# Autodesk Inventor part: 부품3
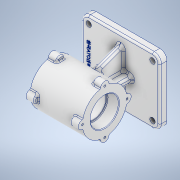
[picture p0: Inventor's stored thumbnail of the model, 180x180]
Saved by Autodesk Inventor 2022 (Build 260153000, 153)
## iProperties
Created: 2023-05
Part Number: 부품3
Material: 알루미늄 6061
Document SubType Name: Modeling
Designer: Admin
Density: 2.7 g/cm^3
Appearance: 알루미늄 - 평지
Mass: 1215.69 g
Surface Area: 797.962 cm^2
Volume: 450.254 cm^3
Author: Admin
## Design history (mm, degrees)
sketch "스케치1"
  geometry: L1 (-65, 55)-(65, 55); L2 (65, 55)-(65, -55); L3 (65, -55)-(-65, -55); L4 (-65, -55)-(-65, 55); L5 (-91, 0)-(91, 0) reference; L6 (0, -77)-(0, 77) reference; 1 further point
  constraints: 8 end point, 2 parallel, 1 horizontal, 1 perpendicular, 2 other
  dimensions: "d0" = 130 distance of L1.start L1.end; "d1" = 110 distance of L1.end L2.end
extrude "돌출1" new body sketch "스케치1" stored distance "d2" = 12; taper "d3" = 0 deg
sketch "스케치2"
  geometry: L1 (95.889, 76)-(-83.31, 76); L2 (-65, -6)-(65, -6) reference; L3 (-43.5, 76)-(43.5, 76); L4 (43.5, 76)-(43.5, 113); L5 (43.5, 113)-(-43.5, 113); L6 (-43.5, 113)-(-43.5, 76); L7 (0, -29.8)-(0, 136.8) reference; 2 further points
  constraints: 10 end point, 2 horizontal, 2 parallel, 1 perpendicular, 1 point on line, 1 other
  dimensions: "d4" = 82 distance between parallel lines of L2 L1; "d5" = 74 diameter of L5.end L1; "d6" = 87 distance of L4.end L5.end
revolve "회전1" sketch "스케치2" stored, may be unused: angle "d7" = 90 deg
sketch "스케치3"
  geometry: L1 (65, 6)-(-65, 6) reference; L2 (20, 6)-(20, 62.593); L3 (20, 62.593)-(-20, 62.593); L4 (-20, 62.593)-(-20, 6); L5 (20, 6)-(-20, 6); L6 (0, -29.8)-(0, 136.8) reference; 1 further point
  constraints: 8 end point, 3 perpendicular, 2 point on line, 1 collinear, 1 other
  dimensions: "d8" = 40 distance of L2.end L3.end; "d9" = 56.59267 distance of L3.end L4.end
extrude "돌출2" join sketch "스케치3" stored distance "d10" = 10; taper "d11" = 0 deg
sketch "스케치4"
  geometry: L1 (55, 6)-(-55, 6) reference; L2 (-41, 6)-(-14.452, 78.94); L3 (-55, 6)-(-55, -6) reference; 1 further point
  constraints: 2 end point, 1 point on line
  dimensions: "d12" = 110 deg angle of L1 L2; "d13" = 14 distance from line of L3 L2.start
feature "리브1" sketch "스케치4" dims "d14" = 1, "d15" = 10, "d16" = 0, "d17" = 0, "d18" = 1, "d19" = 1
sketch "스케치5"
  geometry: L1 (102.925, 76)-(-132.789, 76); L2 (65, -6)-(-65, -6) reference; L3 (-43.5, 39)-(-43.5, 113) reference; L4 (-43.5, 76)-(-24.5, 76); L5 (-24.5, 76)-(-24.5, 99.5); L6 (-24.5, 99.5)-(-43.5, 99.5); L7 (-43.5, 99.5)-(-43.5, 76); L8 (-24.5, 76)-(24.5, 76); L9 (24.5, 76)-(24.5, 97); L10 (24.5, 97)-(-24.5, 97); L11 (-24.5, 97)-(-24.5, 76); L12 (43.5, 39)-(43.5, 113) reference; L13 (24.5, 76)-(43.5, 76); L14 (43.5, 76)-(43.5, 99.5); L15 (43.5, 99.5)-(24.5, 99.5); L16 (24.5, 99.5)-(24.5, 76); L17 (0, -29.8)-(0, 136.8) reference; 5 further points
  constraints: 26 end point, 6 parallel, 4 horizontal, 3 perpendicular, 1 midpoint, 1 point on line
  dimensions: "d20" = 82 distance between parallel lines of L2 L1; "d21" = 47 diameter of L6.end L1; "d22" = 47 diameter of L14.end L1; "d23" = 42 diameter of L9.end L1; "d24" = 19 distance of L5.end L6.end; "d25" = 19 distance of L14.end L15.end
revolve "회전2" sketch "스케치5" stored, may be unused: angle "d26" = 90 deg
sketch "스케치6"
  geometry: L1 (107.2, 0)-(-69.2, 0) reference; C1 r 23.5 at (0, 0) reference; C2 r 7 at (-37, 0); 2 further points
  constraints: 1 centre point, 1 horizontal alignment, 1 point on line, 1 other
  dimensions: "d56" = 14 diameter of C2
extrude "돌출3" join sketch "스케치6" distance "d28" = 14; taper "d29" = 0 deg
fillet "모깎기1" dims "d43" = 12
sketch "스케치8"
  geometry: C1 r 4.5 at (-53, 43); A1 r 12 centre (-53, 43) between (-53, 55) and (-65, 43) reference; 1 further point
  constraints: 1 centre point, 1 coincident
  dimensions: "d44" = 9 diameter of C1
extrude "돌출4" cut sketch "스케치8" distance "d45" = 14; taper "d46" = 0 deg
fillet "모깎기2" dims "d47" = 1
chamfer "모따기1" distance "d48" = 1; stored, may be unused: second distance "d49" = 2, angle "d50" = 45 deg
fillet "모깎기3" dims "d51" = 3
fillet "모깎기4" dims "d52" = 3
fillet "모깎기6" dims "d57" = 2
sketch "스케치9"
  geometry: C1 r 4.5 at (-53, -43) reference; 2 further points
  constraints: 1 horizontal alignment, 1 vertical alignment, 1 other
feature "엠보싱1" sketch "스케치9" dims "d0" = 130, "d1" = 110, "d54" = 0.5, "d55" = 0
sketch "스케치11"
  geometry: A1 r 7 centre (-74, 0) between (-74.746, 6.96) and (-74.746, -6.96) reference; 2 further points
  constraints: 1 coincident
hole "구멍3" sketch "스케치11" at (-74, 0) diameter "d68" = 3.242; stored, may be unused: countersink angle "d72" = 90 deg, drill point angle "d74" = 118 deg; dims "d69" = 8, "d70" = 4, "d71" = 2, "d73" = 10
node "솔리드1"
mirror "미러1"
pattern_circular "원형 패턴1" dims angle "d31" = 360 deg
mirror "미러2"
mirror "미러4"
mirror "미러5"
pattern_circular "원형 패턴4" dims angle "d76" = 360 deg
mirror "미러7"
node "투영된 루프1"
feature "A9D066F2-1C7D-4E18-AEED-F7BC21143FA4" dims "d68" = 3.242, "d69" = 8, "d70" = 4, "d71" = 2, "d72" = 90 deg, "d73" = 10, "d74" = 118 deg
